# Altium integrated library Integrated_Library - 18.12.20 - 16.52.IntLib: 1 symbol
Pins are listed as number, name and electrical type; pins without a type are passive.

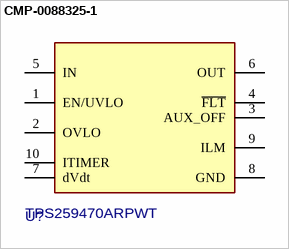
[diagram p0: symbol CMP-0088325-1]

## CMP-0088325-1
designator U?, comment TPS259470ARPWT
2.7- 23V, 5.5 A, 28 mΩ Reverse Current Blocking eFuse with Input Reverse Polarity Protection; Manufacturer: Texas Instruments; Standoff Height: 0mm; Min Supply Voltage: 2.7V; Number Of Outputs: 1; Reset Type: Active Low; SizeZ_mm: 1mm; Threshold Voltage: 1.2/1.1V; Reset Timeout: 100ms; TJmax_C: +125°C; Nominal Supply Current: 430uA; AEC Qualified: No
footprint RPW0010A-MFG
pins: 1 EN/UVLO, 2 OVLO, 3 AUX_OFF (oc), 4 ~{FLT} (oc), 5 IN (power), 6 OUT, 7 dVdt, 8 GND (power), 9 ILM, 10 ITIMER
